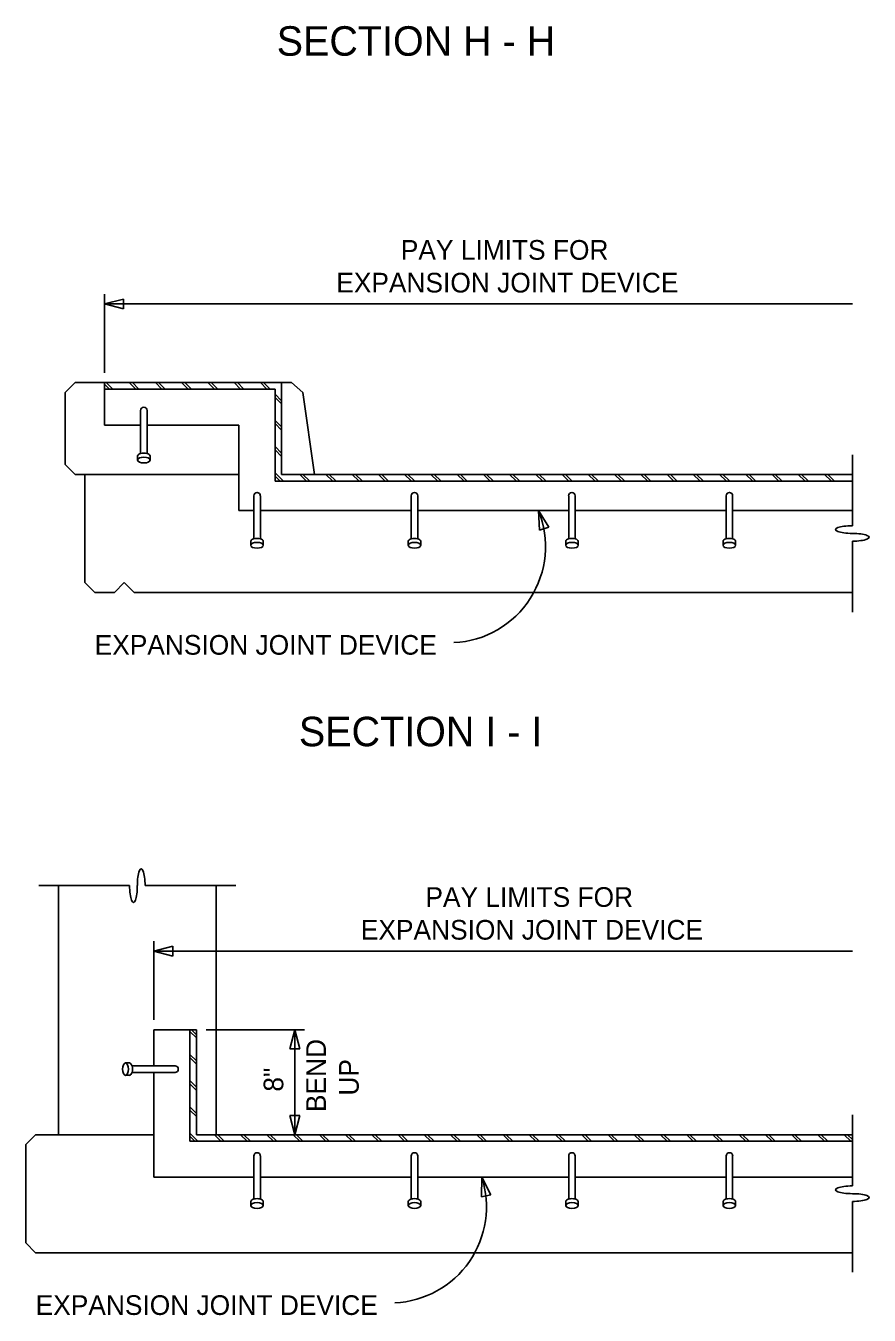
# Model space of a CAD drawing. Extents: x 19590 to 20151, y 19944 to 20103.
# Drawn here: x 19852.46 to 19872.45, y 20019.19 to 20049.78 of the extents above; entities that cross this region are included whole.
import ezdxf

# ---------------------------------------------------------------- set-up
doc = ezdxf.new("R2010")
doc.units = 0
for name, color, linetype in [('DETAIL_PR', 7, 'Continuous'), ('DETAIL_TEXT_DIMEN_PR', 7, 'Continuous'), ('Level 1', 7, 'Continuous'), ('MT_PAVT_MRKGS_EX_REF', 7, 'Continuous')]:
    doc.layers.add(name, color=color, linetype=linetype)

# ---------------------------------------------------------------- blocks, each defined once
blk = doc.blocks.new('EJ3H')
at = {"layer": 'MT_PAVT_MRKGS_EX_REF'}
blk.add_text('SECTION H - H', height=0.69987, dxfattribs=at).set_placement((46.783, -47.04))

msp = doc.modelspace()

# ---------------------------------------------------------------- linework, layer by layer
at = {"layer": 'DETAIL_PR'}
for p, q in [((19853.626, 20041.311), (19853.392, 20041.078)), ((19853.626, 20041.311), (19854.325, 20041.311)), ((19854.325, 20041.311), (19858.524, 20041.311)), ((19854.442, 20041.156), (19854.325, 20041.272)), ((19854.325, 20041.156), (19858.369, 20041.156)), ((19854.326, 20040.3), (19854.326, 20041.311)), ((19854.52, 20041.156), (19854.364, 20041.311)), ((19855.064, 20041.156), (19854.909, 20041.311)), ((19855.142, 20041.156), (19854.986, 20041.311)), ((19855.686, 20041.156), (19855.531, 20041.311)), ((19855.764, 20041.156), (19855.608, 20041.311)), ((19856.308, 20041.156), (19856.153, 20041.311)), ((19856.386, 20041.156), (19856.23, 20041.311)), ((19856.93, 20041.156), (19856.775, 20041.311)), ((19857.008, 20041.156), (19856.852, 20041.311)), ((19857.552, 20041.156), (19857.397, 20041.311)), ((19857.63, 20041.156), (19857.474, 20041.311)), ((19858.174, 20041.156), (19858.019, 20041.311)), ((19858.252, 20041.156), (19858.097, 20041.311)), ((19858.369, 20041.156), (19858.369, 20038.978)), ((19858.524, 20041.311), (19858.524, 20039.134)), ((19858.524, 20041.311), (19858.757, 20041.311)), ((19859.024, 20041.08), (19858.757, 20041.311)), ((19853.393, 20039.367), (19853.393, 20041.078)), ((19858.524, 20040.883), (19858.369, 20041.039)), ((19858.524, 20040.806), (19858.369, 20040.961)), ((19859.024, 20041.08), (19859.302, 20039.134)), ((19855.181, 20040.65), (19855.181, 20039.63)), ((19855.336, 20040.65), (19855.336, 20039.63)), ((19854.325, 20040.3), (19855.181, 20040.3)), ((19855.336, 20040.3), (19857.513, 20040.3)), ((19857.513, 20040.3), (19857.513, 20038.279)), ((19858.524, 20040.261), (19858.369, 20040.417)), ((19858.524, 20040.184), (19858.369, 20040.339)), ((19855.111, 20039.57), (19855.111, 20039.474)), ((19855.406, 20039.57), (19855.406, 20039.474)), ((19858.524, 20039.639), (19858.369, 20039.795)), ((19858.524, 20039.562), (19858.369, 20039.717)), ((19872.053, 20037.918), (19872.053, 20039.6)), ((19853.626, 20039.134), (19853.392, 20039.367)), ((19853.626, 20039.134), (19857.513, 20039.134)), ((19853.859, 20036.568), (19853.859, 20039.134)), ((19858.563, 20038.979), (19858.369, 20039.173)), ((19858.485, 20038.979), (19858.369, 20039.095)), ((19858.369, 20038.978), (19872.053, 20038.978)), ((19858.524, 20039.134), (19872.053, 20039.134)), ((19859.107, 20038.979), (19858.952, 20039.134)), ((19859.185, 20038.979), (19859.03, 20039.134)), ((19859.729, 20038.979), (19859.574, 20039.134)), ((19859.807, 20038.979), (19859.652, 20039.134)), ((19860.351, 20038.979), (19860.196, 20039.134)), ((19860.429, 20038.979), (19860.274, 20039.134)), ((19860.973, 20038.979), (19860.818, 20039.134)), ((19861.051, 20038.979), (19860.896, 20039.134)), ((19861.595, 20038.979), (19861.44, 20039.134)), ((19861.673, 20038.979), (19861.518, 20039.134)), ((19862.217, 20038.979), (19862.062, 20039.134)), ((19862.295, 20038.979), (19862.14, 20039.134)), ((19862.839, 20038.979), (19862.684, 20039.134)), ((19862.917, 20038.979), (19862.762, 20039.134)), ((19863.461, 20038.979), (19863.306, 20039.134)), ((19863.539, 20038.979), (19863.384, 20039.134)), ((19864.083, 20038.979), (19863.928, 20039.134)), ((19864.161, 20038.979), (19864.006, 20039.134)), ((19864.705, 20038.979), (19864.55, 20039.134)), ((19864.783, 20038.979), (19864.628, 20039.134)), ((19865.327, 20038.979), (19865.172, 20039.134)), ((19865.405, 20038.979), (19865.25, 20039.134)), ((19865.949, 20038.979), (19865.794, 20039.134)), ((19866.027, 20038.979), (19865.872, 20039.134)), ((19866.572, 20038.979), (19866.416, 20039.134)), ((19866.649, 20038.979), (19866.494, 20039.134)), ((19867.194, 20038.979), (19867.038, 20039.134)), ((19867.271, 20038.979), (19867.116, 20039.134)), ((19867.816, 20038.979), (19867.66, 20039.134)), ((19867.893, 20038.979), (19867.738, 20039.134)), ((19868.438, 20038.979), (19868.282, 20039.134)), ((19868.515, 20038.979), (19868.36, 20039.134)), ((19869.06, 20038.979), (19868.904, 20039.134)), ((19869.137, 20038.979), (19868.982, 20039.134)), ((19869.682, 20038.979), (19869.526, 20039.134)), ((19869.759, 20038.979), (19869.604, 20039.134)), ((19870.304, 20038.979), (19870.148, 20039.134)), ((19870.381, 20038.979), (19870.226, 20039.134)), ((19870.926, 20038.979), (19870.77, 20039.134)), ((19871.003, 20038.979), (19870.848, 20039.134)), ((19871.548, 20038.979), (19871.392, 20039.134)), ((19871.625, 20038.979), (19871.47, 20039.134)), ((19857.863, 20038.628), (19857.863, 20037.607)), ((19858.019, 20038.628), (19858.019, 20037.607)), ((19861.595, 20038.628), (19861.595, 20037.607)), ((19861.751, 20038.628), (19861.751, 20037.607)), ((19865.328, 20038.628), (19865.328, 20037.607)), ((19865.483, 20038.628), (19865.483, 20037.607)), ((19869.06, 20038.628), (19869.06, 20037.607)), ((19869.215, 20038.628), (19869.215, 20037.607)), ((19857.513, 20038.279), (19857.863, 20038.279)), ((19858.019, 20038.279), (19861.595, 20038.279)), ((19861.751, 20038.279), (19865.328, 20038.279)), ((19865.483, 20038.279), (19869.06, 20038.279)), ((19869.215, 20038.279), (19872.053, 20038.279)), ((19857.793, 20037.548), (19857.793, 20037.453)), ((19858.089, 20037.548), (19858.089, 20037.453)), ((19861.526, 20037.548), (19861.526, 20037.453)), ((19861.821, 20037.548), (19861.821, 20037.453)), ((19865.258, 20037.548), (19865.258, 20037.453)), ((19865.553, 20037.548), (19865.553, 20037.453)), ((19868.99, 20037.548), (19868.99, 20037.453)), ((19869.285, 20037.548), (19869.285, 20037.453)), ((19872.053, 20035.868), (19872.053, 20037.551)), ((19853.859, 20036.568), (19854.092, 20036.335)), ((19854.792, 20036.568), (19854.559, 20036.335)), ((19854.792, 20036.568), (19855.025, 20036.335)), ((19854.092, 20036.335), (19854.559, 20036.335)), ((19855.025, 20036.335), (19872.053, 20036.335)), ((19852.771, 20029.381), (19854.92, 20029.381)), ((19853.237, 20029.381), (19853.237, 20023.472)), ((19855.287, 20029.381), (19857.436, 20029.381)), ((19856.969, 20029.381), (19856.969, 20023.472)), ((19855.492, 20025.96), (19856.503, 20025.96)), ((19855.492, 20025.96), (19855.492, 20025.105)), ((19856.347, 20025.96), (19856.347, 20023.317)), ((19856.503, 20025.766), (19856.347, 20025.921)), ((19856.503, 20025.844), (19856.386, 20025.96)), ((19856.503, 20025.96), (19856.503, 20023.472)), ((19856.503, 20025.222), (19856.347, 20025.377)), ((19856.503, 20025.144), (19856.347, 20025.299)), ((19854.917, 20025.175), (19854.822, 20025.175)), ((19855.997, 20025.105), (19854.977, 20025.105)), ((19855.997, 20024.95), (19854.977, 20024.95)), ((19855.492, 20024.95), (19855.492, 20022.462)), ((19854.917, 20024.88), (19854.822, 20024.88)), ((19856.503, 20024.6), (19856.347, 20024.755)), ((19856.503, 20024.522), (19856.347, 20024.677)), ((19856.503, 20023.978), (19856.347, 20024.133)), ((19856.503, 20023.9), (19856.347, 20024.055)), ((19872.053, 20022.256), (19872.053, 20023.939)), ((19852.693, 20023.472), (19852.46, 20023.239)), ((19852.693, 20023.472), (19855.492, 20023.472)), ((19856.541, 20023.317), (19856.347, 20023.511)), ((19856.464, 20023.317), (19856.347, 20023.433)), ((19856.503, 20023.472), (19872.053, 20023.472)), ((19857.086, 20023.317), (19856.93, 20023.472)), ((19857.164, 20023.317), (19857.008, 20023.472)), ((19857.708, 20023.317), (19857.552, 20023.472)), ((19857.786, 20023.317), (19857.63, 20023.472)), ((19858.33, 20023.317), (19858.174, 20023.472)), ((19858.408, 20023.317), (19858.252, 20023.472)), ((19858.952, 20023.317), (19858.796, 20023.472)), ((19859.03, 20023.317), (19858.874, 20023.472)), ((19859.574, 20023.317), (19859.418, 20023.472)), ((19859.652, 20023.317), (19859.496, 20023.472)), ((19860.196, 20023.317), (19860.04, 20023.472)), ((19860.274, 20023.317), (19860.118, 20023.472)), ((19860.818, 20023.317), (19860.662, 20023.472)), ((19860.896, 20023.317), (19860.74, 20023.472)), ((19861.44, 20023.317), (19861.284, 20023.472)), ((19861.518, 20023.317), (19861.362, 20023.472)), ((19862.062, 20023.317), (19861.906, 20023.472)), ((19862.14, 20023.317), (19861.984, 20023.472)), ((19862.684, 20023.317), (19862.528, 20023.472)), ((19862.762, 20023.317), (19862.606, 20023.472)), ((19863.306, 20023.317), (19863.15, 20023.472)), ((19863.384, 20023.317), (19863.228, 20023.472)), ((19863.928, 20023.317), (19863.773, 20023.472)), ((19864.006, 20023.317), (19863.85, 20023.472)), ((19864.55, 20023.317), (19864.395, 20023.472)), ((19864.628, 20023.317), (19864.472, 20023.472)), ((19865.172, 20023.317), (19865.017, 20023.472)), ((19865.25, 20023.317), (19865.094, 20023.472)), ((19865.794, 20023.317), (19865.639, 20023.472)), ((19865.872, 20023.317), (19865.716, 20023.472)), ((19866.416, 20023.317), (19866.261, 20023.472)), ((19866.494, 20023.317), (19866.338, 20023.472)), ((19867.038, 20023.317), (19866.883, 20023.472)), ((19867.116, 20023.317), (19866.96, 20023.472)), ((19867.66, 20023.317), (19867.505, 20023.472)), ((19867.738, 20023.317), (19867.582, 20023.472)), ((19868.282, 20023.317), (19868.127, 20023.472)), ((19868.36, 20023.317), (19868.204, 20023.472)), ((19868.904, 20023.317), (19868.749, 20023.472)), ((19868.982, 20023.317), (19868.826, 20023.472)), ((19869.526, 20023.317), (19869.371, 20023.472)), ((19869.604, 20023.317), (19869.448, 20023.472)), ((19870.148, 20023.317), (19869.993, 20023.472)), ((19870.226, 20023.317), (19870.071, 20023.472)), ((19870.77, 20023.317), (19870.615, 20023.472)), ((19870.848, 20023.317), (19870.693, 20023.472)), ((19871.392, 20023.317), (19871.237, 20023.472)), ((19871.47, 20023.317), (19871.315, 20023.472)), ((19872.014, 20023.317), (19871.859, 20023.472)), ((19872.053, 20023.356), (19871.937, 20023.472)), ((19852.46, 20023.239), (19852.46, 20020.906)), ((19856.347, 20023.317), (19872.053, 20023.317)), ((19857.863, 20022.967), (19857.863, 20021.947)), ((19858.019, 20022.967), (19858.019, 20021.947)), ((19861.595, 20022.967), (19861.595, 20021.947)), ((19861.751, 20022.967), (19861.751, 20021.947)), ((19865.328, 20022.967), (19865.328, 20021.947)), ((19865.483, 20022.967), (19865.483, 20021.947)), ((19869.06, 20022.967), (19869.06, 20021.947)), ((19869.215, 20022.967), (19869.215, 20021.947)), ((19855.492, 20022.462), (19857.864, 20022.462)), ((19858.019, 20022.462), (19861.596, 20022.462)), ((19861.751, 20022.462), (19865.328, 20022.462)), ((19865.483, 20022.462), (19869.06, 20022.462)), ((19869.215, 20022.462), (19872.053, 20022.462)), ((19857.793, 20021.887), (19857.793, 20021.791)), ((19858.089, 20021.887), (19858.089, 20021.791)), ((19861.526, 20021.887), (19861.526, 20021.791)), ((19861.821, 20021.887), (19861.821, 20021.791)), ((19865.258, 20021.887), (19865.258, 20021.791)), ((19865.553, 20021.887), (19865.553, 20021.791)), ((19868.99, 20021.887), (19868.99, 20021.791)), ((19869.285, 20021.887), (19869.285, 20021.791)), ((19872.053, 20020.207), (19872.053, 20021.889)), ((19852.693, 20020.673), (19852.46, 20020.906)), ((19852.693, 20020.673), (19872.053, 20020.673))]:
    msp.add_line(p, q, dxfattribs=at)
for centre, start, end in [((19855.259, 20040.65), 0, 180), ((19857.941, 20038.629), 0, 180), ((19861.673, 20038.629), 0, 180), ((19865.405, 20038.629), 0, 180), ((19869.137, 20038.629), 0, 180), ((19855.997, 20025.027), 270, 90), ((19857.941, 20022.967), 0, 180), ((19861.674, 20022.967), 0, 180), ((19865.406, 20022.967), 0, 180), ((19869.138, 20022.967), 0, 180)]:
    msp.add_arc(centre, 0.0778, start, end, dxfattribs=at)
for centre, major_axis, ratio, start_param, end_param in [((19855.259, 20039.57), (0.148, 0), 0.466726, 0, 3.141593), ((19872.053, 20037.826), (0.398, 0), 0.230204, 1.570796, 4.712389), ((19872.053, 20037.643), (0.398, 0), 0.230206, 4.712389, 7.853982), ((19857.941, 20037.549), (0.148, 0), 0.466726, 0, 3.141593), ((19861.673, 20037.549), (0.148, 0), 0.466726, 0, 3.141593), ((19865.405, 20037.549), (0.148, 0), 0.466726, 0, 3.141593), ((19869.137, 20037.549), (0.148, 0), 0.466726, 0, 3.141593), ((19855.195, 20029.381), (0, -0.398), 0.230204, 1.570796, 4.712389), ((19855.011, 20029.381), (0, -0.398), 0.230206, 4.712389, 7.853982), ((19854.918, 20025.027), (0, -0.148), 0.466726, 0, 3.141593), ((19872.053, 20022.164), (0.398, 0), 0.230204, 1.570796, 4.712389), ((19857.941, 20021.887), (0.148, 0), 0.466726, 0, 3.141593), ((19861.674, 20021.887), (0.148, 0), 0.466726, 0, 3.141593), ((19865.406, 20021.887), (0.148, 0), 0.466726, 0, 3.141593), ((19869.138, 20021.887), (0.148, 0), 0.466726, 0, 3.141593), ((19872.053, 20021.981), (0.398, 0), 0.230206, 4.712389, 7.853982)]:
    msp.add_ellipse(centre, major_axis=major_axis, ratio=ratio, start_param=start_param, end_param=end_param, dxfattribs=at)
for centre, major_axis in [((19855.259, 20039.475), (0.148, 0)), ((19857.941, 20037.453), (0.148, 0)), ((19861.673, 20037.453), (0.148, 0)), ((19865.405, 20037.453), (0.148, 0)), ((19869.137, 20037.453), (0.148, 0)), ((19854.822, 20025.027), (0, -0.148)), ((19857.941, 20021.792), (0.148, 0)), ((19861.674, 20021.792), (0.148, 0)), ((19865.406, 20021.792), (0.148, 0)), ((19869.138, 20021.792), (0.148, 0))]:
    msp.add_ellipse(centre, major_axis=major_axis, ratio=0.466726, dxfattribs=at)
at = {"layer": 'DETAIL_TEXT_DIMEN_PR'}
for p, q in [((19854.326, 20041.544), (19854.326, 20043.41)), ((19854.325, 20043.177), (19872.053, 20043.177)), ((19855.492, 20026.194), (19855.492, 20028.06)), ((19855.492, 20027.827), (19872.053, 20027.827)), ((19856.736, 20025.96), (19859.069, 20025.96)), ((19858.835, 20023.472), (19858.835, 20025.96))]:
    msp.add_line(p, q, dxfattribs=at)
for centre, end in [((19862.497, 20037.422), 22.0583), ((19861.098, 20021.761), 17.8929)]:
    msp.add_arc(centre, 2.281, 272.7697, end, dxfattribs=at)
at = {"layer": 'Level 1'}
for p, q in [((19854.777, 20043.294), (19854.326, 20043.177)), ((19854.777, 20043.06), (19854.777, 20043.294)), ((19854.326, 20043.177), (19854.777, 20043.06)), ((19864.636, 20037.813), (19864.611, 20038.279)), ((19864.611, 20038.279), (19864.858, 20037.883)), ((19864.858, 20037.883), (19864.636, 20037.813)), ((19855.944, 20027.943), (19855.492, 20027.826)), ((19855.944, 20027.71), (19855.944, 20027.943)), ((19855.492, 20027.826), (19855.944, 20027.71)), ((19858.719, 20025.508), (19858.835, 20025.96)), ((19858.835, 20025.96), (19858.952, 20025.508)), ((19858.952, 20025.508), (19858.719, 20025.508)), ((19858.952, 20023.924), (19858.719, 20023.924)), ((19858.719, 20023.924), (19858.835, 20023.472)), ((19858.835, 20023.472), (19858.952, 20023.924)), ((19863.259, 20021.995), (19863.269, 20022.461)), ((19863.269, 20022.461), (19863.486, 20022.049)), ((19863.486, 20022.049), (19863.259, 20021.995))]:
    msp.add_line(p, q, dxfattribs=at)

# ---------------------------------------------------------------- block references
msp.add_blockref('EJ3H', (19811.624, 20096.106), dxfattribs=at)

# ---------------------------------------------------------------- texts
at = {"layer": 'DETAIL_TEXT_DIMEN_PR'}
for s, height, p in [('PAY LIMITS FOR', 0.46652, (19861.349, 20044.227)), ('EXPANSION JOINT DEVICE', 0.46652, (19859.819, 20043.45)), ('EXPANSION JOINT DEVICE', 0.46652, (19854.092, 20034.858)), ('SECTION I - I', 0.69987, (19858.933, 20032.686)), ('PAY LIMITS FOR', 0.46652, (19861.932, 20028.876)), ('EXPANSION JOINT DEVICE', 0.46652, (19860.402, 20028.099)), ('EXPANSION JOINT DEVICE', 0.46652, (19852.693, 20019.196))]:
    msp.add_text(s, height=height, dxfattribs=at).set_placement(p)
for s, p in [('BEND', (19859.574, 20024.009)), ('UP', (19860.351, 20024.399)), ('8"', (19858.563, 20024.493))]:
    msp.add_text(s, height=0.4665, rotation=90, dxfattribs=at).set_placement(p)

doc.saveas('drawing.dxf')
